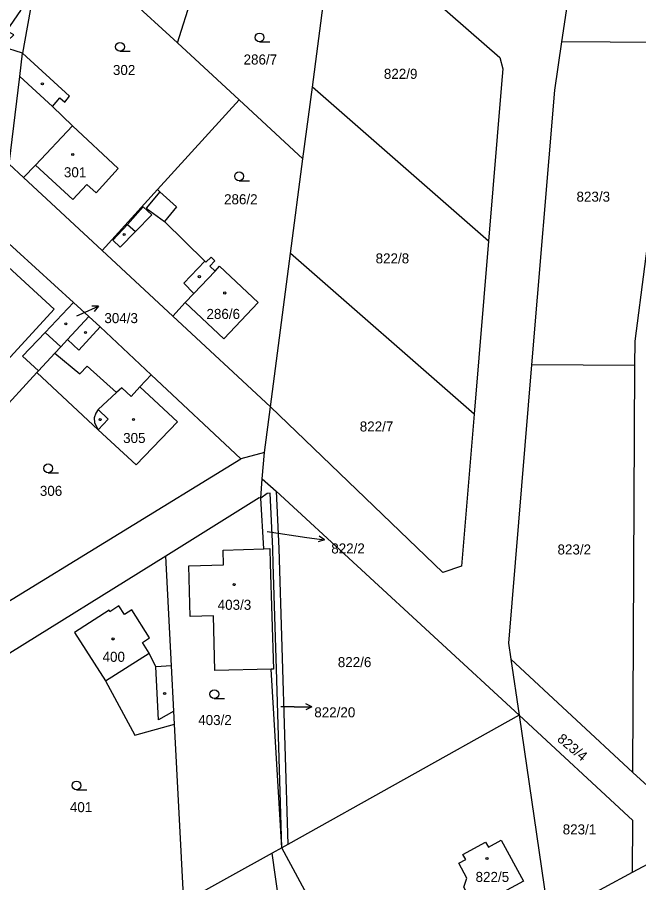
# Model space of a CAD drawing. Extents: x -724107 to -720612, y -1045267 to -1038441.
# Drawn here: x -722551.9 to -722446.5, y -1042409.8 to -1042263.1 of the extents above; entities that cross this region are included whole.
import ezdxf

# ---------------------------------------------------------------- set-up
doc = ezdxf.new("R2010")
doc.units = 0
for name, color, linetype in [('Hranice parcel', 7, 'Continuous'), ('Parcelní čísla', 7, 'Continuous'), ('Pop  PČ popisy', 7, 'Continuous'), ('Vnitřní kresba', 7, 'Continuous'), ('Značky budov', 7, 'Continuous'), ('Značky kultur', 7, 'Continuous')]:
    doc.layers.add(name, color=color, linetype=linetype)

msp = doc.modelspace()

# ---------------------------------------------------------------- linework, layer by layer
at = {"layer": 'Hranice parcel'}
for p, q in [((-722524.74, -1042267.44), (-722513.36, -1042231.31)), ((-722455.74, -1042240.69), (-722459.6, -1042267.26)), ((-722501.84, -1042274.96), (-722497.97, -1042245.5)), ((-722547.09, -1042246.82), (-722550.97, -1042269.19)), ((-722547.09, -1042246.82), (-722524.74, -1042267.44)), ((-722524.74, -1042267.44), (-722514.28, -1042277.1)), ((-722440.58, -1042267.35), (-722459.6, -1042267.26)), ((-722503.44, -1042287.1), (-722501.84, -1042274.96)), ((-722471.96, -1042301.07), (-722501.84, -1042274.96)), ((-722514.28, -1042277.1), (-722528.12, -1042292.3)), ((-722503.44, -1042287.1), (-722514.28, -1042277.1)), ((-722505.55, -1042303.16), (-722503.44, -1042287.1)), ((-722553.23, -1042288.01), (-722550.81, -1042290.25)), ((-722550.81, -1042290.25), (-722537.5, -1042302.6)), ((-722528.12, -1042292.3), (-722537.5, -1042302.6)), ((-722542.36, -1042311.42), (-722559.85, -1042295.48)), ((-722471.96, -1042301.07), (-722474.4, -1042330.37)), ((-722537.5, -1042302.6), (-722525.51, -1042313.75)), ((-722508.97, -1042329.15), (-722505.55, -1042303.16)), ((-722474.4, -1042330.37), (-722505.55, -1042303.16)), ((-722539.74, -1042313.81), (-722542.36, -1042311.42)), ((-722525.51, -1042313.75), (-722508.97, -1042329.15)), ((-722447.15, -1042322.1), (-722464.67, -1042322.02)), ((-722447.49, -1042391.12), (-722447.15, -1042322.1)), ((-722558.13, -1042333.61), (-722548.56, -1042323.3)), ((-722548.56, -1042323.3), (-722548.3, -1042323.03)), ((-722513.98, -1042337.96), (-722529.19, -1042323.7)), ((-722509.99, -1042336.88), (-722508.97, -1042329.15)), ((-722509.99, -1042336.88), (-722513.98, -1042337.96)), ((-722510.33, -1042341.32), (-722509.99, -1042336.88)), ((-722559.19, -1042365.71), (-722513.98, -1042337.96)), ((-722510.58, -1042344.62), (-722510.33, -1042341.32)), ((-722510.33, -1042341.32), (-722508.01, -1042343.45)), ((-722510.06, -1042353.21), (-722510.58, -1042344.62)), ((-722508.01, -1042343.45), (-722466.81, -1042381.39)), ((-722526.71, -1042354.43), (-722559.28, -1042374.71)), ((-722525.73, -1042373.06), (-722526.71, -1042354.43)), ((-722468.2, -1042371.92), (-722447.49, -1042391.12)), ((-722468.2, -1042371.92), (-722466.81, -1042381.39)), ((-722507.01, -1042403.89), (-722508.83, -1042373.6)), ((-722466.81, -1042381.39), (-722506.03, -1042403.34)), ((-722466.81, -1042381.39), (-722461.77, -1042415.67)), ((-722523.64, -1042413.1), (-722525.22, -1042382.92)), ((-722441.52, -1042396.65), (-722447.49, -1042391.12)), ((-722506.03, -1042403.34), (-722507.01, -1042403.89)), ((-722491.85, -1042432.03), (-722507.01, -1042403.89)), ((-722447.57, -1042408.03), (-722441.56, -1042404.8)), ((-722461.77, -1042415.67), (-722447.57, -1042408.03))]:
    msp.add_line(p, q, dxfattribs=at)
for points in [[(-722497.97, -1042245.5), (-722470.05, -1042269.89), (-722469.53, -1042271.82), (-722469.75, -1042274.4), (-722471.96, -1042301.07)], [(-722550.97, -1042269.19), (-722554.54, -1042268.01), (-722552.46, -1042266.06), (-722553.64, -1042265.4), (-722551.26, -1042261.94), (-722549.85, -1042253.03), (-722556.19, -1042250.63), (-722560.5, -1042259.74), (-722562.51, -1042261.99), (-722564.8, -1042260.05), (-722568.81, -1042264.12), (-722568.07, -1042264.83), (-722570.92, -1042267.86), (-722566.4, -1042272.11), (-722568.28, -1042274.11)], [(-722459.6, -1042267.26), (-722460.8, -1042275.43), (-722464.67, -1042322.02)], [(-722447.15, -1042322.1), (-722447.13, -1042318.01), (-722440.58, -1042267.35)], [(-722553.23, -1042288.01), (-722551.44, -1042273.13), (-722550.97, -1042269.19)], [(-722550.81, -1042290.25), (-722548.8, -1042288.13), (-722542.48, -1042293.96), (-722540.07, -1042291.44), (-722538.52, -1042292.85), (-722534.79, -1042288.75), (-722542.49, -1042281.49), (-722545.91, -1042278.19), (-722544.67, -1042276.74), (-722543.84, -1042277.45), (-722543, -1042276.47), (-722550.97, -1042269.19)], [(-722528.12, -1042292.3), (-722527.71, -1042292.67), (-722524.89, -1042295.23), (-722526.89, -1042297.72), (-722520.07, -1042304.43), (-722519.89, -1042304.61), (-722519.03, -1042303.73), (-722518.36, -1042304.38), (-722519.22, -1042305.26), (-722518.35, -1042306.12), (-722517.57, -1042305.29), (-722511.04, -1042311.44), (-722516.86, -1042317.62), (-722523.39, -1042311.47), (-722525.51, -1042313.75)], [(-722553.02, -1042320.66), (-722554.22, -1042321.97), (-722559.54, -1042317.12), (-722558.41, -1042315.85), (-722564.49, -1042310.45), (-722556.96, -1042302.18), (-722545.65, -1042312.57), (-722553.02, -1042320.66)], [(-722548.3, -1042323.03), (-722550.98, -1042320.54), (-722547.17, -1042316.51), (-722542.36, -1042311.42)], [(-722548.3, -1042323.03), (-722545.52, -1042320.03), (-722544.52, -1042318.95), (-722543.39, -1042317.74), (-722539.74, -1042313.81)], [(-722529.19, -1042323.7), (-722537.84, -1042315.59), (-722539.74, -1042313.81)], [(-722464.67, -1042322.02), (-722468.6, -1042369.18), (-722468.2, -1042371.92)], [(-722548.56, -1042323.3), (-722538.14, -1042333.02), (-722531.74, -1042338.99), (-722524.74, -1042331.69), (-722531.1, -1042325.76), (-722529.19, -1042323.7)], [(-722474.4, -1042330.37), (-722476.54, -1042356.13), (-722479.75, -1042357.24), (-722508.97, -1042329.15)], [(-722510.58, -1042344.62), (-722510.86, -1042344.56), (-722526.71, -1042354.43)], [(-722507.01, -1042403.89), (-722507.93, -1042373.58), (-722508.48, -1042355.75), (-722508.56, -1042353.17), (-722509, -1042343.79), (-722509.5, -1042343.81), (-722510.58, -1042344.62)], [(-722508.01, -1042343.45), (-722507.56, -1042353.13), (-722506.03, -1042403.34)], [(-722508.83, -1042373.6), (-722518.36, -1042373.84), (-722518.59, -1042364.57), (-722522.56, -1042364.67), (-722522.78, -1042356.11), (-722516.9, -1042355.95), (-722516.98, -1042353.44), (-722510.06, -1042353.21)], [(-722510.06, -1042353.21), (-722509.06, -1042353.18), (-722508.98, -1042355.76), (-722508.43, -1042373.59), (-722508.83, -1042373.6)], [(-722525.73, -1042373.06), (-722528.36, -1042373.2), (-722529.52, -1042370.9), (-722530.67, -1042369.08), (-722529.45, -1042368.3), (-722532.45, -1042363.56), (-722533.7, -1042364.35), (-722534.66, -1042362.9), (-722536.16, -1042363.87), (-722536.32, -1042363.61), (-722542.2, -1042367.4), (-722536.91, -1042375.59), (-722531.96, -1042384.8), (-722525.22, -1042382.92)], [(-722525.22, -1042382.92), (-722525.33, -1042380.72), (-722525.73, -1042373.06)], [(-722447.57, -1042408.03), (-722447.53, -1042399.26), (-722466.81, -1042381.39)], [(-722469.81, -1042402.62), (-722466.03, -1042409.55), (-722474.28, -1042414.01), (-722476.15, -1042410.57), (-722475.63, -1042409.06), (-722477.01, -1042406.51), (-722475.85, -1042405.88), (-722476.33, -1042405.03), (-722472.48, -1042402.92), (-722471.99, -1042403.79), (-722469.81, -1042402.62)], [(-722507.01, -1042403.89), (-722508.67, -1042404.81), (-722523.64, -1042413.1)]]:
    msp.add_lwpolyline(points, dxfattribs=at)
at = {"layer": 'Pop  PČ popisy'}
for p, q in [((-722540.86, -1042313.31), (-722538.12, -1042312.09)), ((-722538.12, -1042312.09), (-722539.24, -1042312.04)), ((-722538.12, -1042312.09), (-722538.83, -1042312.95)), ((-722541.77, -1042313.71), (-722540.86, -1042313.31)), ((-722509.5, -1042350.26), (-722502.76, -1042351.27)), ((-722502.76, -1042351.27), (-722499.79, -1042351.69)), ((-722499.79, -1042351.69), (-722500.85, -1042352.04)), ((-722499.79, -1042351.69), (-722500.71, -1042351.05)), ((-722501.93, -1042380.01), (-722502.93, -1042379.51)), ((-722504.93, -1042380.01), (-722507.19, -1042380.01)), ((-722504.93, -1042380.01), (-722501.93, -1042380.01)), ((-722501.93, -1042380.01), (-722502.93, -1042380.51))]:
    msp.add_line(p, q, dxfattribs=at)
at = {"layer": 'Vnitřní kresba'}
for p, q in [((-722545.91, -1042278.19), (-722551.44, -1042273.13)), ((-722548.8, -1042288.13), (-722542.49, -1042281.49)), ((-722527.71, -1042292.67), (-722530.03, -1042295.44)), ((-722530.53, -1042295.25), (-722533.21, -1042298.19)), ((-722529.05, -1042296.6), (-722530.53, -1042295.25)), ((-722530.03, -1042295.44), (-722526.89, -1042297.72)), ((-722529.05, -1042296.6), (-722531.81, -1042299.41)), ((-722535.65, -1042300.87), (-722533.21, -1042298.19)), ((-722533.21, -1042298.19), (-722531.81, -1042299.41)), ((-722531.81, -1042299.41), (-722534.43, -1042302.08)), ((-722534.43, -1042302.08), (-722535.65, -1042300.87)), ((-722520.07, -1042304.43), (-722523.62, -1042308.18)), ((-722521.93, -1042309.9), (-722518.35, -1042306.12)), ((-722523.62, -1042308.18), (-722521.93, -1042309.9)), ((-722523.39, -1042311.47), (-722521.93, -1042309.9)), ((-722547.17, -1042316.51), (-722544.52, -1042318.95)), ((-722541.46, -1042319.53), (-722537.84, -1042315.59)), ((-722543.39, -1042317.74), (-722541.46, -1042319.53)), ((-722545.52, -1042320.03), (-722541.29, -1042323.52)), ((-722541.29, -1042323.52), (-722540.03, -1042322.26)), ((-722540.03, -1042322.26), (-722535.06, -1042326.71)), ((-722535.06, -1042326.71), (-722538.17, -1042329.61)), ((-722534.18, -1042325.9), (-722535.06, -1042326.71)), ((-722532.59, -1042327.36), (-722534.18, -1042325.9)), ((-722531.1, -1042325.76), (-722532.59, -1042327.36)), ((-722538.17, -1042329.61), (-722538.58, -1042330.18)), ((-722538.17, -1042329.61), (-722536.49, -1042331.25)), ((-722538.58, -1042330.18), (-722538.83, -1042331)), ((-722538.83, -1042331), (-722538.77, -1042331.83)), ((-722536.49, -1042331.25), (-722538.14, -1042333.02)), ((-722538.77, -1042331.83), (-722538.14, -1042333.02)), ((-722536.91, -1042375.59), (-722529.52, -1042370.9)), ((-722527.91, -1042382.22), (-722528.36, -1042373.2)), ((-722525.33, -1042380.72), (-722527.91, -1042382.22)), ((-722506.76, -1042418.49), (-722508.67, -1042404.81))]:
    msp.add_line(p, q, dxfattribs=at)
at = {"layer": 'Značky budov'}
for centre in [(-722547.63, -1042274.35), (-722542.48, -1042286.35), (-722533.74, -1042299.91), (-722521.01, -1042307.06), (-722516.71, -1042309.83), (-722543.64, -1042315.07), (-722540.33, -1042316.54), (-722537.82, -1042331.3), (-722532.17, -1042331.28), (-722515.11, -1042359.28), (-722535.64, -1042368.49), (-722526.89, -1042377.75), (-722472.24, -1042405.72)]:
    msp.add_circle(centre, 0.175, dxfattribs=at)
at = {"layer": 'Značky kultur'}
for p, q in [((-722510.8, -1042267.25), (-722509.05, -1042267.25)), ((-722534.47, -1042268.85), (-722532.72, -1042268.85)), ((-722514.27, -1042290.8), (-722512.52, -1042290.8)), ((-722546.64, -1042340.32), (-722544.89, -1042340.32)), ((-722518.47, -1042378.6), (-722516.72, -1042378.6)), ((-722541.84, -1042394.08), (-722540.09, -1042394.08))]:
    msp.add_line(p, q, dxfattribs=at)
for centre in [(-722510.8, -1042266.5), (-722534.47, -1042268.1), (-722514.27, -1042290.05), (-722546.64, -1042339.57), (-722518.47, -1042377.85), (-722541.84, -1042393.33)]:
    msp.add_circle(centre, 0.75, dxfattribs=at)

# ---------------------------------------------------------------- texts
at = {"layer": 'Parcelní čísla'}
for s, p in [('286/7', (-722513.51, -1042271.09)), ('302', (-722535.66, -1042272.87)), ('822/9', (-722489.72, -1042273.52)), ('301', (-722543.97, -1042290.21)), ('286/2', (-722516.82, -1042294.79)), ('823/3', (-722457.06, -1042294.35)), ('822/8', (-722491.12, -1042304.81)), ('304/3', (-722537.11, -1042314.94)), ('286/6', (-722519.8, -1042314.23)), ('822/7', (-722493.81, -1042333.31)), ('305', (-722533.93, -1042335.27)), ('306', (-722548.05, -1042344.23)), ('822/2', (-722498.64, -1042354)), ('823/2', (-722460.28, -1042354.17)), ('403/3', (-722517.9, -1042363.55)), ('400', (-722537.42, -1042372.37)), ('822/6', (-722497.53, -1042373.27)), ('403/2', (-722521.2, -1042383.09)), ('822/20', (-722501.52, -1042381.78)), ('401', (-722542.96, -1042397.86)), ('823/1', (-722459.4, -1042401.63)), ('822/5', (-722474.17, -1042409.69))]:
    msp.add_text(s, height=1.7, dxfattribs=at).set_placement(p)
msp.add_text('823/4', height=1.7, rotation=320, dxfattribs=at).set_placement((-722460.48, -1042385.68))

doc.saveas('drawing.dxf')
